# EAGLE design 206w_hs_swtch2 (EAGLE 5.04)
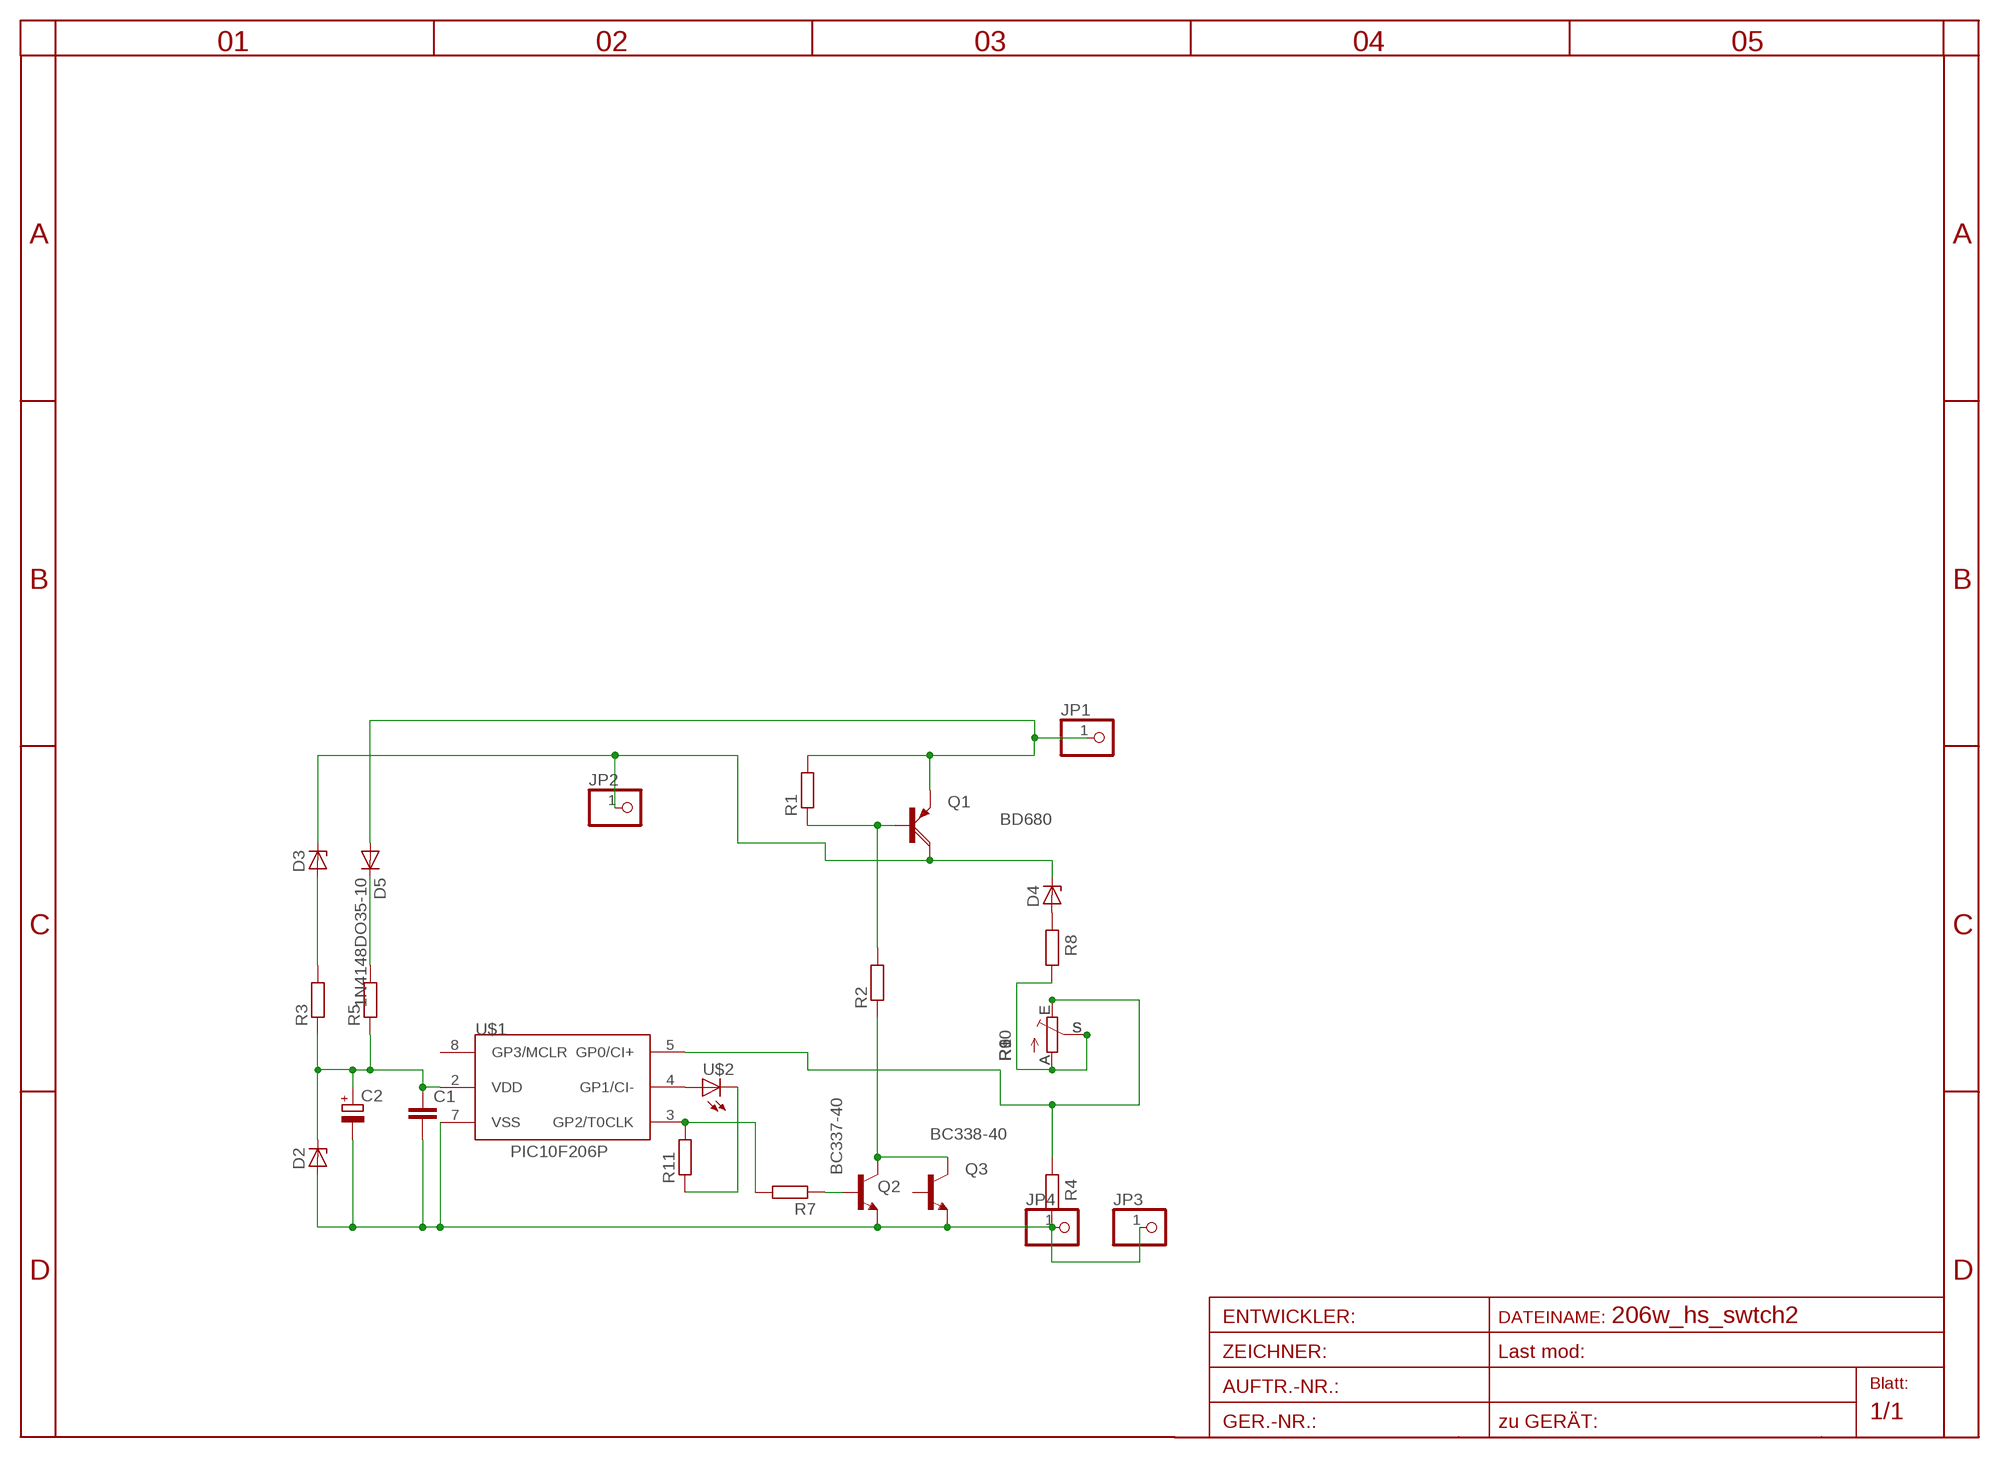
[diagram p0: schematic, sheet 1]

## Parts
C1  C-EU050-030X075  [C050-030X075]
C2  CPOL-EUE2.5-5  [E2,5-5]
D2  ZENER-DIODEZD-7.5  [ZDIO-7.5]
D3  ZENER-DIODEZD-10  [ZDIO-10]
D4  ZENER-DIODEZD-10  [ZDIO-10]
D5  1N4148DO35-10  [DO35-10]
JP1  PINHD-1X1  [1X01]
JP2  PINHD-1X1  [1X01]
JP3  PINHD-1X1  [1X01]
JP4  PINHD-1X1  [1X01]
Q1  BD680  [TO126AV]
Q2  BC337-40  [TO92]
Q3  BC338-40  [TO92-EBC]
R1  R-EU_0207/10  [0207/10]
R2  R-EU_0207/10  [0207/10]
R3  R-EU_0207/10  [0207/10]
R4  R-EU_0207/10  [0207/10]
R5  R-EU_0207/10  [0207/10]
R6  TRIM_EU-CA6V  [CA6V]
R7  R-EU_0207/10  [0207/10]
R8  R-EU_0207/10  [0207/10]
R9  TRIM_EU-CA9V  [CA9V]
R10  TRIM_EU-LI15  [LI15]
R11  R-EU_0207/10  [0207/10]
U$1  PIC10F206P  [DIL8]
U$2  LED3MM  [LED3MM]

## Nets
GND: C1.2 C2.- D2.A JP3.1 JP4.1 Q2.1(E) Q3.E R4.1 U$1.7(VSS)
N$1: D4.A R8.2
N$2: C1.1 C2.+ D2.C R3.1 R5.1 U$1.2(VDD)
N$3: D3.A R3.2
N$4: D5.C R5.2
N$5: U$1.4(GP1/CI-) U$2.A
N$6: R11.1 U$2.K(C)
N$7: R4.2 R6.E R9.E R10.E U$1.5(GP0/CI+)
N$8: R6.A R6.S R8.1 R9.A R9.S R10.A R10.S
N$9: R7.2 R11.2 U$1.3(GP2/T0CLK)
N$10: Q2.2(B) R7.1
N$12: Q2.3(C) Q3.C R2.1
N$13: Q1.B R1.1 R2.2
N$17: D5.A JP1.1 Q1.E R1.2
V60: D3.C D4.C JP2.1 Q1.C
Unconnected: Q3.B U$1.8(GP3/MCLR)

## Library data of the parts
C1 = rcl:C-EU: CAPACITOR, European symbol
C2 = rcl:CPOL-EU: POLARIZED CAPACITOR, European symbol
D2-D4 = diode-1:ZENER-DIODE: Z-Diode
D5 = diode-1:1N4148: DIODE
JP1-JP4 = pinhead:PINHD-1X1: PIN HEADER
Q1 = transistor-power:BD680: PNP DARLINGTON TRANSISTOR
Q2 = transistor-npn:BC337*: NPN Transistor
Q3 = transistor-npn:BC338*: NPN Transistor
R1-R5 R7 R8 R11 = rcl:R-EU_: RESISTOR, European symbol
R6 R9 R10 = pot:TRIM_EU-: POTENTIOMETER
U$1 = microchip-5:PIC10F2*: uPC nW 0,25/0,5k Program Flash memory Comparator
U$2 = led(2):LED: LED

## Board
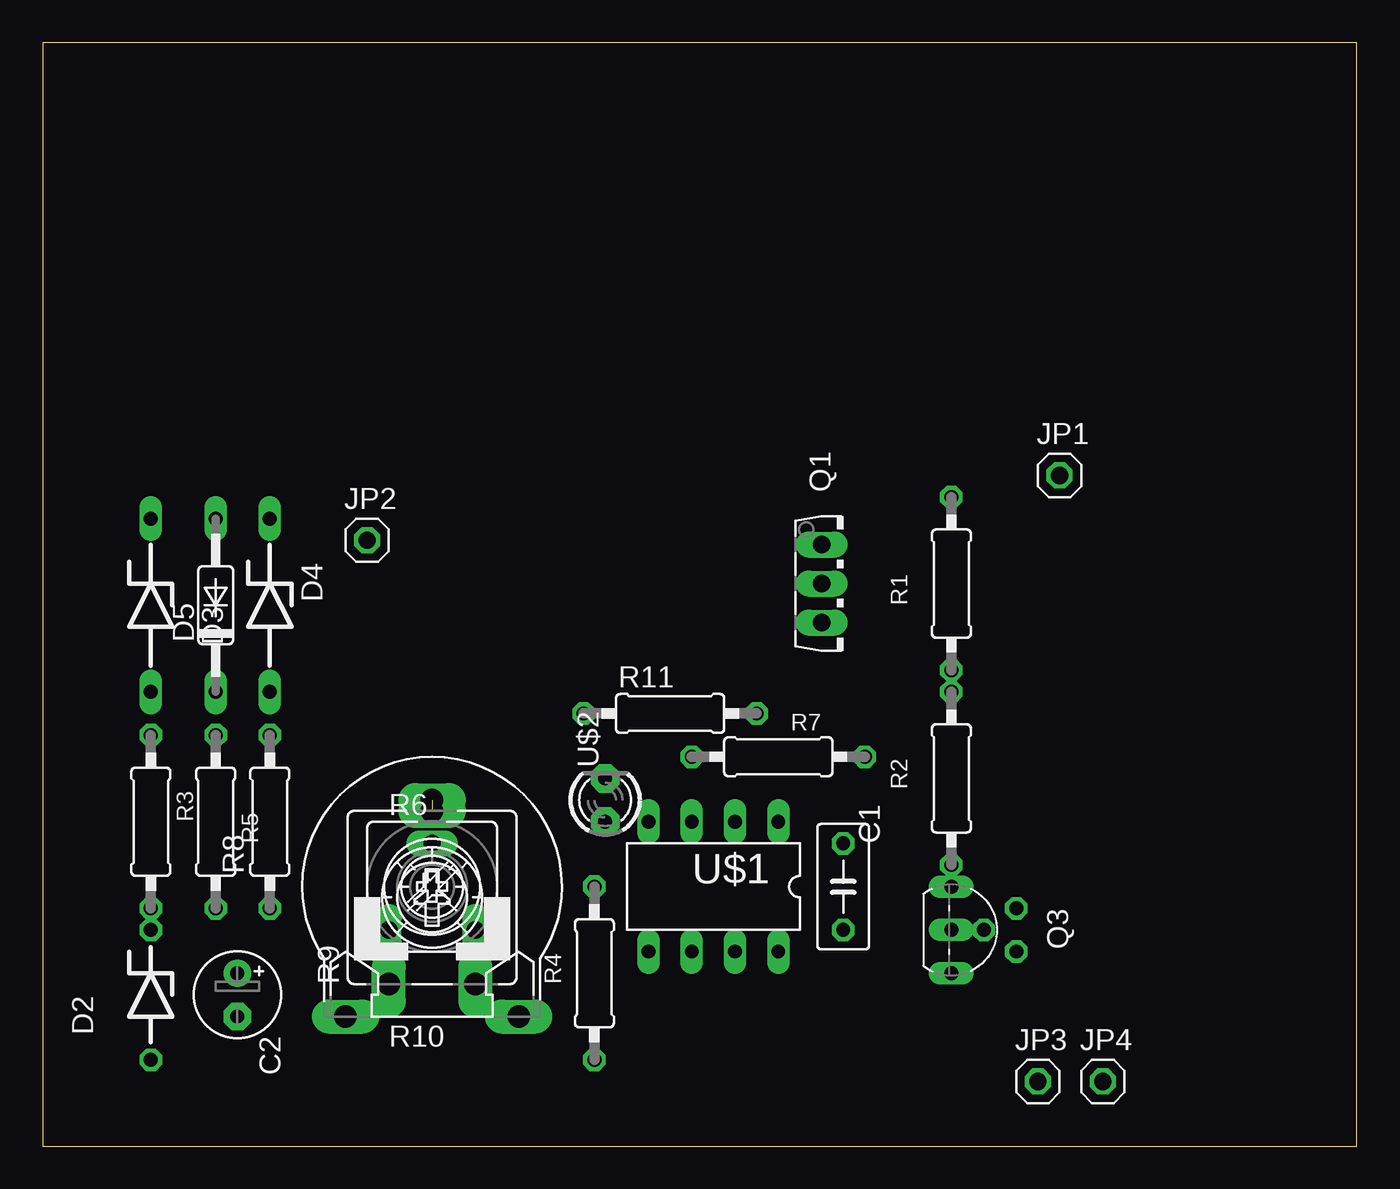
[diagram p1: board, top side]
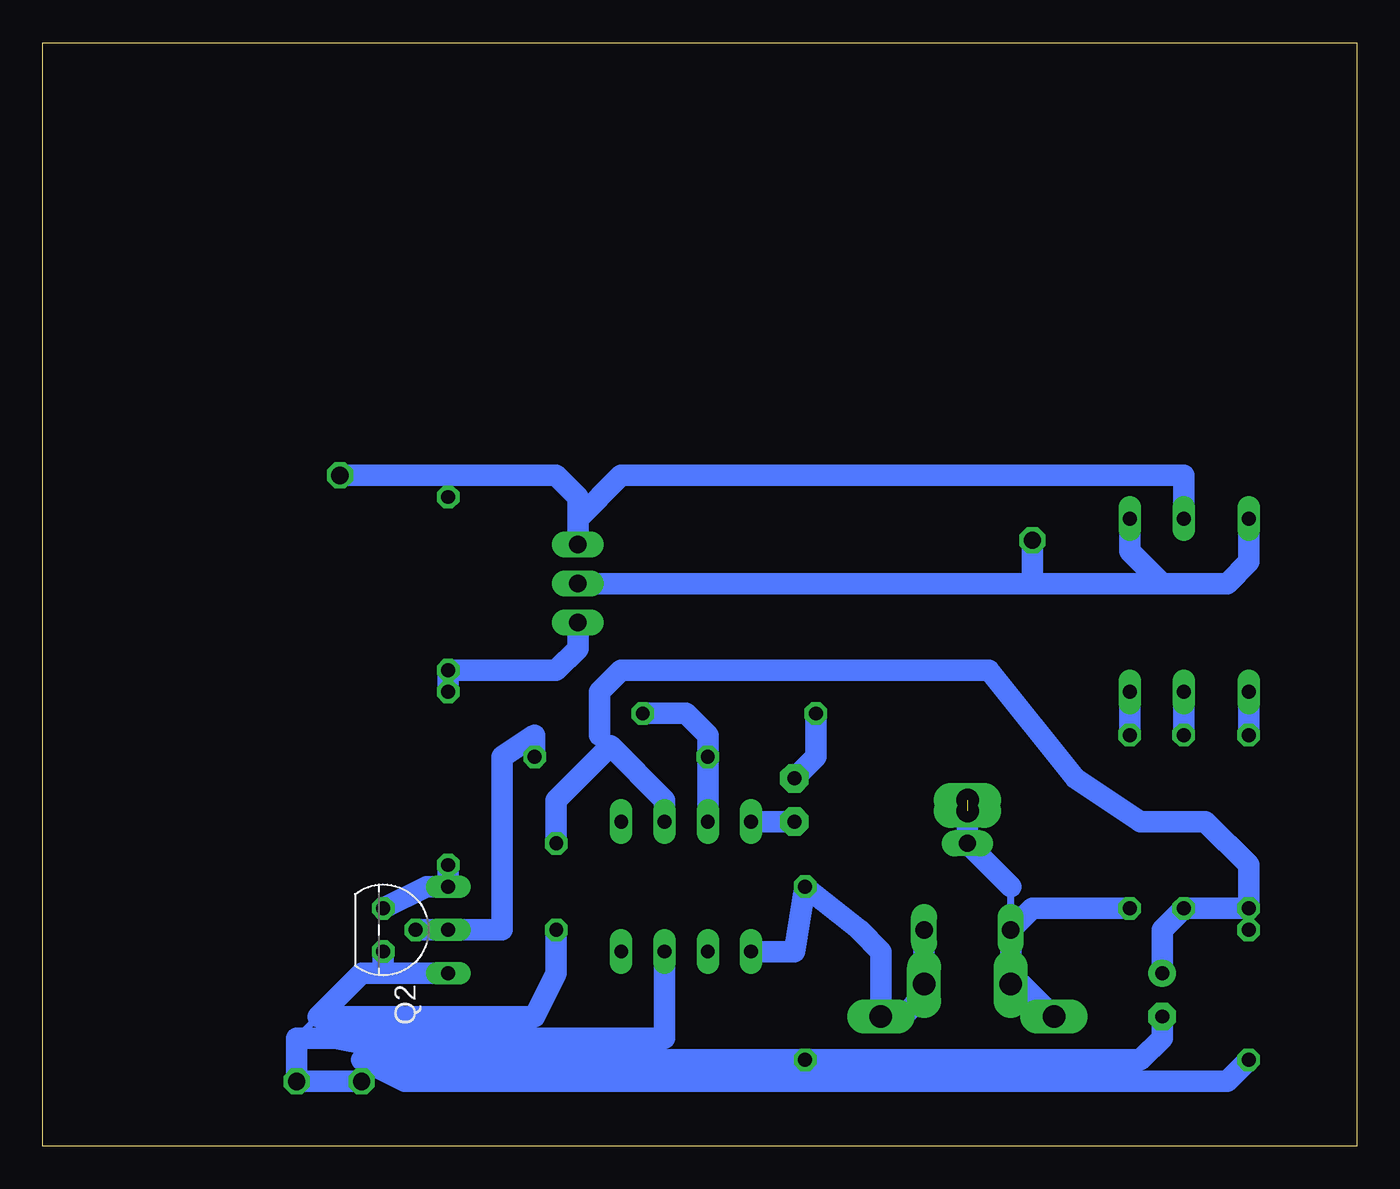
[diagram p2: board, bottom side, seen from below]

Size 77.14 x 64.76 mm. Coordinates in mm from the lower left corner, seen from the top.
Outline: 0,0 77.14,0 77.14,64.76 0,64.76 0,0
Copper layers (1*16): Top 0.035mm / dielectric 1.5mm / Bottom 0.035mm
Design rules "default": minimum track width 10mil, minimum drill 24mil, track to track 8mil, track to pad 8mil, pad to pad 8mil, via to via 8mil, smd to smd 8mil, copper to edge 40mil, drill to drill 8mil, minimum pad ring 10mil, minimum via ring 8mil, stop-mask expansion 4mil, vias tented up to drill 0mil, thermal gap 10mil

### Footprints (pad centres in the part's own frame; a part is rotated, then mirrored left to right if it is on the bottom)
C050-030X075 = drill 0.813 octagon: 1 -2.54,0; 2 2.54,0
E2,5-5 = drill 0.813 pad 1.6 round: + -1.27,0 | drill 0.813 pad 1.6 octagon: - 1.27,0
ZDIO-7.5 = drill 0.813 octagon: A 3.81,0; C -3.81,0
ZDIO-10 = drill 0.813 long: A 5.08,0; C -5.08,0
DO35-10 = drill 0.813 long: A 5.08,0; C -5.08,0
1X01 = drill 1.016 octagon: 1 0,0
TO126AV = drill 1.016 long: B 2.286,-1.27; C 0,-1.27; E -2.286,-1.27
TO92 = drill 0.813 octagon: 1 1.27,0; 2 0,1.905; 3 -1.27,0
TO92-EBC = drill 0.813 long: B 0,-1.27; C -2.54,-1.27; E 2.54,-1.27
0207/10 = drill 0.813 octagon: 1 -5.08,0; 2 5.08,0
CA6V = drill 1.016 long: A -2.54,-2.54; E 2.54,-2.54; S 0,2.54
CA9V = drill 1.321 long: A -2.54,-5.08; E 2.54,-5.08; S 0,5.08
LI15 = drill 1.321 long: A -5.08,-7.62; E 5.08,-7.62; S 0,5.08
DIL8 = drill 0.813 long: 1 -3.81,-3.81; 2 -1.27,-3.81; 3 1.27,-3.81; 4 3.81,-3.81; 5 3.81,3.81; 6 1.27,3.81; 7 -1.27,3.81; 8 -3.81,3.81
LED3MM = drill 0.813 pad 1.676 octagon: A -1.27,0; K 1.27,0

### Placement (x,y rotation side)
C1  46.99,15.24 270 top
C2  11.43,8.89 270 top
D2  6.35,8.89 270 top
D3  6.35,31.75 270 top
D4  13.34,31.75 270 top
D5  10.16,31.75 90 top
JP1  59.69,39.37 0 top
JP2  19.05,35.56 0 top
JP3  58.42,3.81 0 top
JP4  62.23,3.81 0 top
Q1  46.99,33.02 270 top
Q2  57.15,12.7 270 bottom
Q3  54.61,12.7 270 top
R1  53.34,33.02 90 top
R2  53.34,21.59 90 top
R3  6.35,19.05 90 top
R4  32.38,10.16 90 top
R5  10.16,19.05 90 top
R6  22.86,15.24 0 top
R7  43.18,22.86 180 top
R8  13.34,19.05 90 top
R9  22.86,14.61 0 top
R10  22.86,15.24 0 top
R11  36.83,25.4 0 top
U$1  39.37,15.24 180 top
U$2  33.02,20.32 90 top

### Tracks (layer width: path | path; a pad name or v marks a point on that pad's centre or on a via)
GND
  Bottom 0.406: 55.88,5.08 62.23,6.35 60.96,7.62
  Bottom 1.27: D2.A 7.62,3.81 55.88,3.81 58.42,5.08 55.88,5.08 R4.1 12.7,5.08 11.43,6.35 C2.- | 57.15,10.16 Q2.1 | U$1.7 40.64,6.35 62.23,6.35 JP4.1 JP3.1 | C1.2 46.99,10.16 48.26,7.62 60.96,7.62 58.42,10.16 57.15,10.16 | 57.15,10.16 Q3.E
N$1
  Bottom 1.27: R8.2 D4.A
N$2
  Bottom 0.406: 44.45,24.13 43.81,23.5 | R3.1 D2.C
  Bottom 1.27: C2.+ 11.43,12.7 R5.1 R3.1 6.35,16.51 8.89,19.05 12.7,19.05 16.51,21.59 21.59,27.94 43.18,27.94 44.45,26.67 44.45,24.13 | U$1.2 40.64,20.32 43.81,23.5 46.99,20.32 C1.1
N$3
  Bottom 1.27: R3.2 D3.A
N$4
  Bottom 1.27: R5.2 D5.C
N$5
  Bottom 1.27: U$2.A U$1.4
N$6
  Bottom 1.27: U$2.K 31.75,22.86 R11.1
N$7
  Bottom 0.406: R9.E 25.4,8.89 | 26.67,7.62 R10.E
  Bottom 1.27: R9.E R6.E | 25.4,8.89 26.67,7.62 | R10.E 27.94,11.43 29.21,12.7 R4.2 33.02,11.43 U$1.5
N$8  (1 unrouted)
  Bottom 0.406: R6.A 20.32,15.24
  Bottom 1.27: R8.1 19.05,13.97 R6.A R9.A 19.68,9.53 R10.A | R10.S R6.S 20.32,15.24
N$9
  Bottom 1.27: U$1.3 R7.2 38.1,24.13 39.37,25.4 R11.2
N$10
  Bottom 1.27: R7.1 48.26,24.13 50.16,22.86 50.16,12.7 Q2.2
N$12
  Bottom 1.27: Q2.3 54.61,15.24 Q3.C R2.1
N$13
  Bottom 1.27: Q1.B 45.72,29.21 46.99,27.94 R1.1 R2.2
N$17
  Bottom 0.406: 45.72,36.83 Q1.E | 53.34,39.37 R1.2
  Bottom 1.27: D5.A 10.16,39.37 43.18,39.37 45.72,36.83 | Q1.E 45.72,38.1 46.99,39.37 53.34,39.37 JP1.1
V60
  Bottom 1.27: D4.C 13.34,34.92 11.43,33.02 | 11.43,33.02 7.62,33.02 6.35,34.29 D3.C | 11.43,33.02 19.05,33.02 | 19.05,33.02 Q1.C | 19.05,33.02 JP2.1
